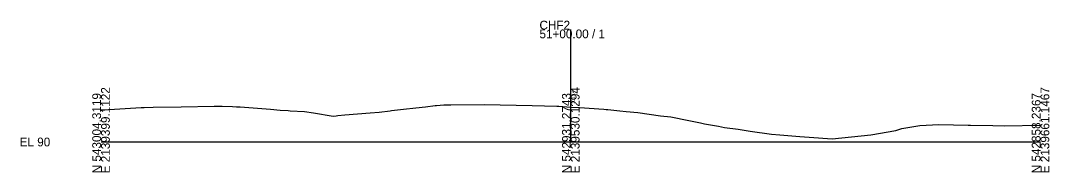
# Model space of a CAD drawing. Extents: x -12831 to 2303, y -10 to 39065.
# Drawn here: x 1974.3 to 2302.8, y 1990.3 to 2038.7 of the extents above; entities that cross this region are included whole.
import ezdxf

# ---------------------------------------------------------------- set-up
doc = ezdxf.new("R2010")
doc.units = 0
for name, color, linetype in [('RD_GPK_XS_Cell', 7, 'Continuous'), ('RD_XS_ExGround', 7, 'Continuous'), ('RD_XS_TX_Elev_EX', 7, 'Continuous')]:
    doc.layers.add(name, color=color, linetype=linetype)

msp = doc.modelspace()

# ---------------------------------------------------------------- linework, layer by layer
at = {"layer": 'RD_GPK_XS_Cell'}
for p, q in [((2150, 2000), (2150, 2035.86)), ((2000, 2000), (2150, 2000)), ((2150, 2000), (2300, 2000))]:
    msp.add_line(p, q, dxfattribs=at)
at = {"layer": 'RD_XS_ExGround'}
for p, q in [((2004.32, 2010.51), (2012.81, 2010.95)), ((2012.81, 2010.95), (2013.8, 2011)), ((2013.8, 2011), (2016.63, 2011.06)), ((2016.63, 2011.06), (2025.62, 2011.24)), ((2025.62, 2011.24), (2036.13, 2011.43)), ((2036.13, 2011.43), (2038.64, 2011.47)), ((2038.64, 2011.47), (2042.03, 2011.32)), ((2042.03, 2011.32), (2043.27, 2011.26)), ((2043.27, 2011.26), (2043.68, 2011.24)), ((2043.68, 2011.24), (2044.4, 2011.18)), ((2044.4, 2011.18), (2054.15, 2010.42)), ((2096.62, 2010.42), (2100.55, 2010.84)), ((2100.55, 2010.84), (2103.56, 2011.24)), ((2103.56, 2011.24), (2106.66, 2011.62)), ((2106.66, 2011.62), (2107.07, 2011.66)), ((2107.07, 2011.66), (2109.5, 2011.8)), ((2109.5, 2011.8), (2111.65, 2011.83)), ((2111.65, 2011.83), (2122.32, 2011.95)), ((2122.32, 2011.95), (2137.68, 2011.6)), ((2137.68, 2011.6), (2145.59, 2011.42)), ((2145.59, 2011.42), (2146.16, 2011.39)), ((2146.16, 2011.39), (2150, 2011.14)), ((2150, 2011.14), (2152.45, 2010.98)), ((2152.45, 2010.98), (2152.76, 2010.98)), ((2152.76, 2010.98), (2160.55, 2010.47)), ((2000, 2010.16), (2002.43, 2010.34)), ((2002.43, 2010.34), (2004.32, 2010.51)), ((2054.15, 2010.42), (2057.2, 2010.19)), ((2057.2, 2010.19), (2059.73, 2010)), ((2059.73, 2010), (2060.34, 2009.97)), ((2060.34, 2009.97), (2065.02, 2009.69)), ((2065.02, 2009.69), (2067.86, 2009.28)), ((2067.86, 2009.28), (2074.12, 2008.28)), ((2074.12, 2008.28), (2075.06, 2008.39)), ((2075.06, 2008.39), (2075.62, 2008.42)), ((2075.62, 2008.42), (2077.89, 2008.63)), ((2077.89, 2008.63), (2085.98, 2009.32)), ((2085.98, 2009.32), (2088.8, 2009.56)), ((2088.8, 2009.56), (2092.3, 2009.94)), ((2092.3, 2009.94), (2092.76, 2010.01)), ((2092.76, 2010.01), (2096.62, 2010.42)), ((2160.55, 2010.47), (2161.27, 2010.4)), ((2161.27, 2010.4), (2161.85, 2010.33)), ((2161.85, 2010.33), (2165.62, 2009.92)), ((2165.62, 2009.92), (2167.65, 2009.69)), ((2167.65, 2009.69), (2171.38, 2009.35)), ((2171.38, 2009.35), (2178.66, 2008.36)), ((2178.66, 2008.36), (2181.96, 2007.97)), ((2181.96, 2007.97), (2187.73, 2006.83)), ((2187.73, 2006.83), (2191.37, 2006.11)), ((2191.37, 2006.11), (2192.72, 2005.83)), ((2192.72, 2005.83), (2193.39, 2005.71)), ((2193.39, 2005.71), (2197.13, 2005.04)), ((2197.13, 2005.04), (2199.04, 2004.67)), ((2199.04, 2004.67), (2203.47, 2004.04)), ((2253.75, 2003.63), (2255.71, 2004.26)), ((2255.71, 2004.26), (2257.61, 2004.58)), ((2257.61, 2004.58), (2261.51, 2005.24)), ((2261.51, 2005.24), (2267.55, 2005.55)), ((2267.55, 2005.55), (2276.94, 2005.39)), ((2276.94, 2005.39), (2277.68, 2005.37)), ((2277.68, 2005.37), (2284.73, 2005.23)), ((2284.73, 2005.23), (2288.4, 2005.18)), ((2288.4, 2005.18), (2300, 2005.37)), ((2203.47, 2004.04), (2207.27, 2003.49)), ((2207.27, 2003.49), (2214.05, 2002.49)), ((2214.05, 2002.49), (2216.79, 2002.27)), ((2216.79, 2002.27), (2223.13, 2001.74)), ((2223.13, 2001.74), (2226.1, 2001.52)), ((2226.1, 2001.52), (2233.42, 2001)), ((2233.42, 2001), (2245.85, 2002.26)), ((2245.85, 2002.26), (2253.75, 2003.63))]:
    msp.add_line(p, q, dxfattribs=at)

# ---------------------------------------------------------------- texts
at = {"layer": 'RD_GPK_XS_Cell'}
for s, p in [('CHF2', (2140, 2035.86)), ('51+00.00 / 1', (2140, 2033.06)), ('EL 90', (1974, 1998.6))]:
    msp.add_text(s, height=2.8, dxfattribs=at).set_placement(p)
for s, p in [('E 2139399.1122', (2002.8, 1990)), ('E 2139530.1294', (2152.8, 1990)), ('E 2139661.1467', (2302.8, 1990)), ('N 543004.3119', (2000, 1990)), ('N 542931.2743', (2150, 1990)), ('N 542858.2367', (2300, 1990))]:
    msp.add_text(s, height=2.8, rotation=90, dxfattribs=at).set_placement(p)
at = {"layer": 'RD_XS_TX_Elev_EX'}
msp.add_text('101.14', height=1, rotation=90, dxfattribs=at).set_placement((2151.25, 2012.14))

doc.saveas('drawing.dxf')
